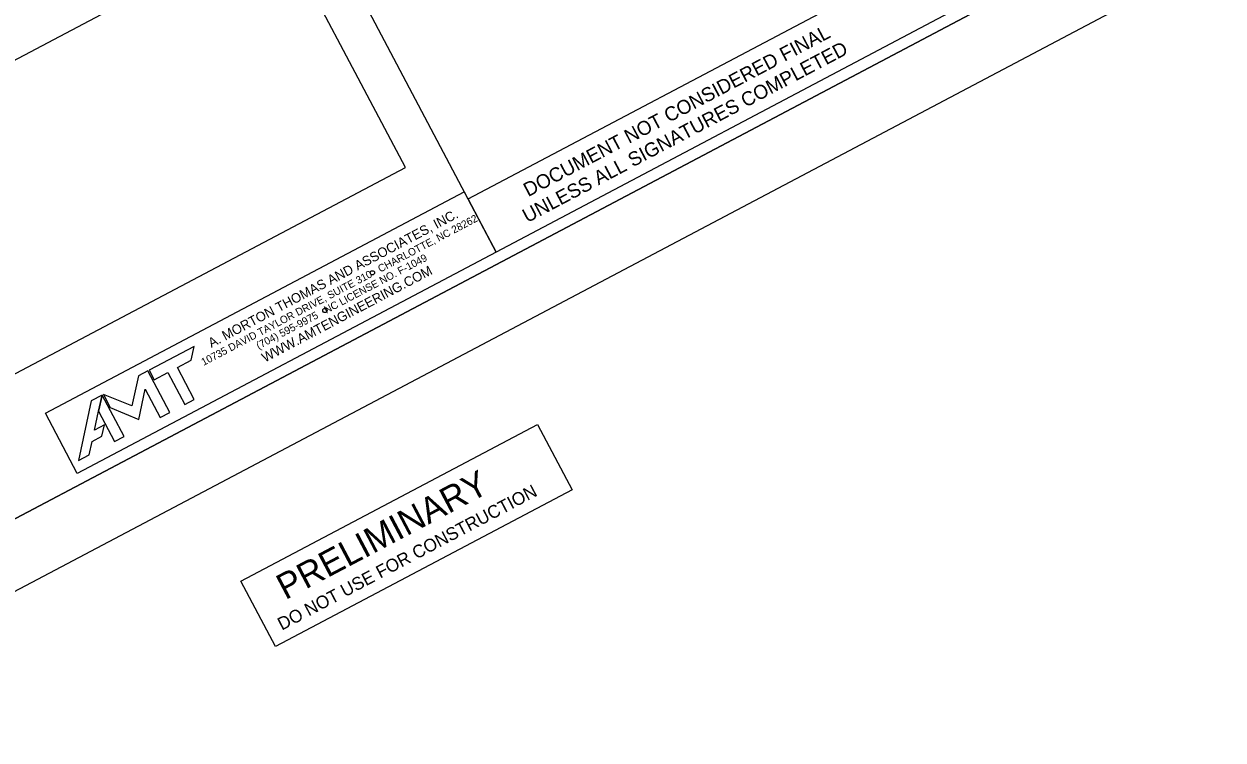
# Model space of a CAD drawing. Extents: x 1487052 to 1489663, y 496209 to 500965.
# Drawn here: x 1488633 to 1489101.4, y 498333.7 to 498613.3 of the extents above; entities that cross this region are included whole.
import ezdxf

# ---------------------------------------------------------------- set-up
doc = ezdxf.new("R2010")
doc.units = 0
for name, color, linetype in [('DEV PRELIMINARY STAMP CELL', 7, 'Continuous'), ('DEV TYPE 3 BARRICADE SINGLE WITH R11-2 CELL', 7, 'Continuous'), ('Gray Area Fill Shapes', 7, 'Continuous'), ('Prop Grid Mask', 7, 'Continuous'), ('Scratch_Level_0', 7, 'Continuous'), ('Scratch_Level_2', 7, 'Continuous'), ('Scratch_Level_3', 7, 'Continuous'), ('Sheet Block Title CELL', 7, 'Continuous'), ('Sheet Plot Border Outside CELL', 7, 'Continuous'), ('Sheet Sticker Exception Certification CELL', 7, 'Continuous')]:
    doc.layers.add(name, color=color, linetype=linetype)

msp = doc.modelspace()

# ---------------------------------------------------------------- linework, layer by layer
at = {"layer": 'DEV PRELIMINARY STAMP CELL'}
msp.add_lwpolyline([(1488717.77, 498395.82), (1488833.62, 498456.99), (1488847.12, 498431.43), (1488731.27, 498370.26)], close=True, dxfattribs=at)
msp.add_lwpolyline([(1488717.77, 498395.82), (1488833.62, 498456.99), (1488847.12, 498431.43), (1488731.27, 498370.26)], close=True, dxfattribs=at)
at = {"layer": 'DEV TYPE 3 BARRICADE SINGLE WITH R11-2 CELL'}
msp.add_lwpolyline([(1488799.26, 499640.64), (1487561.25, 498986.94), (1488004.83, 498146.86), (1488782, 498557.22), (1488726.77, 498661.8), (1489187.62, 498905.14)], close=True, dxfattribs=at)
at = {"layer": 'Gray Area Fill Shapes'}
msp.add_lwpolyline([(1488717.77, 498395.82), (1488833.62, 498456.99), (1488847.12, 498431.43), (1488731.27, 498370.26)], close=True, dxfattribs=at)
at = {"layer": 'Prop Grid Mask'}
msp.add_lwpolyline([(1488641.41, 498461.38), (1488805.03, 498547.78), (1488817.47, 498524.23), (1488653.84, 498437.83)], close=True, dxfattribs=at)
at = {"layer": 'Scratch_Level_0'}
for points in [[(1488820.13, 499708.2), (1487493.69, 499007.81), (1487983.96, 498079.29), (1489310.41, 498779.69)], [(1488753.26, 498645.82), (1488930.15, 498739.23), (1488994.36, 498617.63), (1488817.47, 498524.23)]]:
    msp.add_lwpolyline(points, close=True, dxfattribs=at)
at = {"layer": 'Scratch_Level_2'}
msp.add_lwpolyline([(1488291.16, 498594.06), (1488757.84, 498840.48), (1488829.46, 498704.84), (1488362.78, 498458.43)], close=True, dxfattribs=at)
at = {"layer": 'Scratch_Level_3'}
msp.add_lwpolyline([(1487493.69, 499007.81), (1488662.1, 499625.77), (1488820.13, 499708.2), (1489310.41, 498779.69), (1487983.96, 498079.29)], close=True, dxfattribs=at)
msp.add_lwpolyline([(1487493.69, 499007.81), (1488662.1, 499625.77), (1488820.13, 499708.2), (1489310.41, 498779.69), (1487983.96, 498079.29)], close=True, dxfattribs=at)
at = {"layer": 'Sheet Block Title CELL'}
msp.add_lwpolyline([(1488641.41, 498461.38), (1488805.03, 498547.78), (1488817.47, 498524.23), (1488653.84, 498437.83)], close=True, dxfattribs=at)
for points in [[(1488699.58, 498466.73), (1488692.99, 498479.2), (1488698.37, 498482.04), (1488699.51, 498487.39), (1488681.91, 498478.09), (1488683.86, 498474.38), (1488689.28, 498477.24), (1488695.87, 498464.77), (1488699.58, 498466.73)], [(1488677.89, 498458.93), (1488680.43, 498470.75), (1488686.26, 498459.7), (1488689.97, 498461.66), (1488681.43, 498477.84), (1488677.72, 498475.88), (1488675.11, 498464.18), (1488664.05, 498468.66), (1488666.77, 498463.51), (1488677.89, 498458.93)], [(1488662.16, 498462.11), (1488663.58, 498468.41), (1488659.24, 498466.12), (1488654.35, 498442.85), (1488658.55, 498445.07), (1488659.65, 498450.3), (1488663.49, 498452.33), (1488664.52, 498456.78), (1488660.54, 498454.68), (1488662.16, 498462.11)], [(1488672.12, 498452.24), (1488663.58, 498468.41), (1488662.16, 498462.11), (1488668.41, 498450.28), (1488672.12, 498452.24)]]:
    msp.add_lwpolyline(points, dxfattribs=at)
for centre in [(1488769.13, 498516.16), (1488750.59, 498501.45)]:
    msp.add_circle(centre, 0.833, dxfattribs=at)
at = {"layer": 'Sheet Plot Border Outside CELL'}
msp.add_lwpolyline([(1487851.5, 497981.08), (1489344.19, 498769.26), (1488830.57, 499741.98), (1487337.88, 498953.8)], close=True, dxfattribs=at)
at = {"layer": 'Sheet Sticker Exception Certification CELL'}
for p, q in [((1488806.49, 498545.01), (1488983.38, 498638.41)), ((1488994.36, 498617.63), (1488817.47, 498524.23)), ((1488817.47, 498524.23), (1488806.49, 498545.01))]:
    msp.add_line(p, q, dxfattribs=at)

# ---------------------------------------------------------------- texts
at = {"layer": 'DEV PRELIMINARY STAMP CELL'}
for s, height, p in [(' PRELIMINARY', 9.9999, (1488731.85, 498386.57)), ('DO NOT USE FOR CONSTRUCTION', 5.0001, (1488733.76, 498376.41))]:
    msp.add_text(s, height=height, rotation=27.8351, dxfattribs=at).set_placement(p)
at = {"layer": 'Sheet Block Title CELL'}
for s, height, p in [('10735 DAVID TAYLOR DRIVE, SUITE 310   CHARLOTTE, NC 28262', 2.9167, (1488703.22, 498479.79)), ('A. MORTON THOMAS AND ASSOCIATES, INC.', 3.75, (1488706.22, 498486.79)), ('(704) 595-9975   NC LICENSE NO. F-1049', 2.9167, (1488724.71, 498486.19)), ('WWW.AMTENGINEERING.COM', 3.75, (1488727.14, 498481.11))]:
    msp.add_text(s, height=height, rotation=27.8346, dxfattribs=at).set_placement(p)
at = {"layer": 'Sheet Sticker Exception Certification CELL'}
for s, p in [('DOCUMENT NOT CONSIDERED FINAL', (1488829.96, 498545.7)), ('UNLESS ALL SIGNATURES COMPLETED', (1488829.58, 498535.55))]:
    msp.add_text(s, height=5.5, rotation=27.8351, dxfattribs=at).set_placement(p)

doc.saveas('drawing.dxf')
